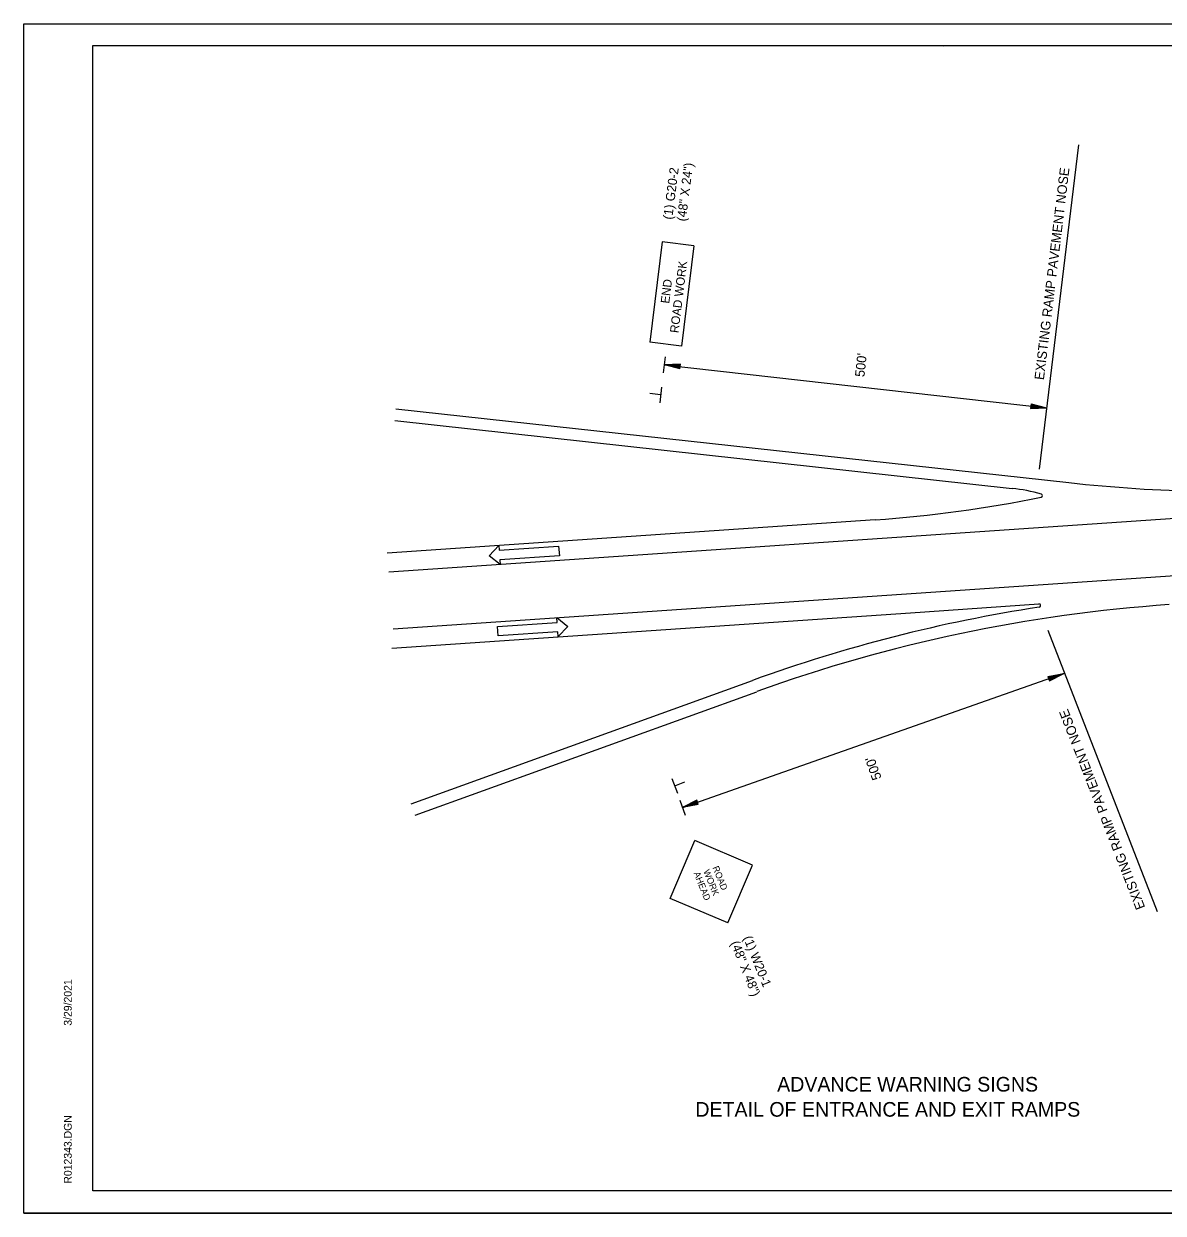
# Model space of a CAD drawing. Extents: x 1397271 to 1411271, y 376395 to 377888.
# Drawn here: x 1399604 to 1401035, y 376395 to 377888 of the extents above; entities that cross this region are included whole.
import ezdxf

# ---------------------------------------------------------------- set-up
doc = ezdxf.new("R2010")
doc.units = 0
for name, color, linetype in [('Default', 7, 'Continuous'), ('R_Border', 7, 'Continuous'), ('R_Draft', 7, 'Continuous'), ('R_Exist Surface', 7, 'Continuous'), ('R_MOT', 7, 'Continuous'), ('R_No Plot', 7, 'Continuous')]:
    doc.layers.add(name, color=color, linetype=linetype)

msp = doc.modelspace()

# ---------------------------------------------------------------- linework, layer by layer
at = {"layer": 'R_Border'}
for p, q in [((1399691.2, 377860.7), (1401904.5, 377860.7)), ((1399691.2, 376422.5), (1399691.2, 377860.7)), ((1400758.8, 377858.9), (1400758.8, 377858.9)), ((1400758.8, 377858.9), (1400758.8, 377858.9)), ((1399691.2, 376422.5), (1399691.2, 376422.5)), ((1401904.5, 376422.5), (1399691.2, 376422.5))]:
    msp.add_line(p, q, dxfattribs=at)
at = {"layer": 'R_Draft'}
for p, q in [((1400428.9, 377460.6), (1400408.7, 377459.8)), ((1400428.9, 377460.6), (1400408.7, 377459.8)), ((1400428.2, 377454.6), (1400408.7, 377459.8)), ((1400428.2, 377454.6), (1400408.7, 377459.8)), ((1400428.8, 377460.1), (1400412, 377459.4)), ((1400428.8, 377460.1), (1400412, 377459.4)), ((1400428.3, 377455.1), (1400412, 377459.4)), ((1400428.3, 377455.1), (1400412, 377459.4)), ((1400428.8, 377459.6), (1400415.4, 377459.1)), ((1400428.8, 377459.6), (1400415.4, 377459.1)), ((1400428.3, 377455.6), (1400415.4, 377459.1)), ((1400428.3, 377455.6), (1400415.4, 377459.1)), ((1400428.7, 377459.1), (1400418.7, 377458.7)), ((1400428.7, 377459.1), (1400418.7, 377458.7)), ((1400428.4, 377456.1), (1400418.7, 377458.7)), ((1400428.4, 377456.1), (1400418.7, 377458.7)), ((1400428.6, 377458.6), (1400422.1, 377458.3)), ((1400428.6, 377458.6), (1400422.1, 377458.3)), ((1400428.4, 377456.6), (1400422.1, 377458.3)), ((1400428.4, 377456.6), (1400422.1, 377458.3)), ((1400428.6, 377458), (1400425.4, 377457.9)), ((1400428.6, 377458), (1400425.4, 377457.9)), ((1400428.5, 377457.1), (1400425.4, 377457.9)), ((1400428.5, 377457.1), (1400425.4, 377457.9)), ((1400428.2, 377454.6), (1400428.9, 377460.6)), ((1400428.2, 377454.6), (1400428.9, 377460.6)), ((1400869.2, 377411), (1400868.6, 377405)), ((1400869.1, 377410), (1400882, 377406.5)), ((1400869.2, 377411), (1400888.8, 377405.8)), ((1400869.2, 377410.5), (1400885.4, 377406.1)), ((1400868.6, 377405.5), (1400885.4, 377406.1)), ((1400868.6, 377405), (1400888.8, 377405.8)), ((1400868.7, 377406.5), (1400878.7, 377406.9)), ((1400868.7, 377406), (1400882, 377406.5)), ((1400868.8, 377407.5), (1400872, 377407.6)), ((1400868.8, 377407), (1400875.3, 377407.3)), ((1400868.9, 377408.5), (1400872, 377407.6)), ((1400869, 377409), (1400875.3, 377407.3)), ((1400869.1, 377409.5), (1400878.7, 377406.9)), ((1400890.3, 377068.6), (1400910.2, 377072.4)), ((1400890.3, 377068.6), (1400892.3, 377063)), ((1400890.5, 377068.2), (1400907, 377071.3)), ((1400890.6, 377067.7), (1400903.8, 377070.2)), ((1400890.8, 377067.2), (1400900.6, 377069.1)), ((1400891, 377066.7), (1400897.4, 377068)), ((1400891.2, 377066.2), (1400894.3, 377066.8)), ((1400891.5, 377065.4), (1400894.3, 377066.8)), ((1400891.6, 377064.9), (1400897.4, 377068)), ((1400891.8, 377064.4), (1400900.6, 377069.1)), ((1400892, 377063.9), (1400903.8, 377070.2)), ((1400892.1, 377063.4), (1400907, 377071.3)), ((1400892.3, 377063), (1400910.2, 377072.4)), ((1400449.4, 376913.2), (1400431.5, 376903.8)), ((1400451.4, 376907.6), (1400431.5, 376903.8)), ((1400433.3, 376904.7), (1400431.5, 376903.8)), ((1400433.5, 376904.1), (1400431.5, 376903.8)), ((1400433.3, 376904.7), (1400431.8, 376903.9)), ((1400433.5, 376904.2), (1400431.8, 376903.9)), ((1400433.3, 376904.6), (1400432.2, 376904)), ((1400433.5, 376904.2), (1400432.2, 376904)), ((1400433.4, 376904.6), (1400432.5, 376904.1)), ((1400433.5, 376904.3), (1400432.5, 376904.1)), ((1400433.4, 376904.5), (1400432.8, 376904.2)), ((1400433.4, 376904.3), (1400432.8, 376904.2)), ((1400433.4, 376904.5), (1400433.1, 376904.3)), ((1400433.4, 376904.4), (1400433.1, 376904.3)), ((1400433.5, 376904.1), (1400433.3, 376904.7)), ((1400449.6, 376912.8), (1400434.7, 376904.9)), ((1400451.2, 376908), (1400434.7, 376904.9)), ((1400449.7, 376912.3), (1400437.9, 376906)), ((1400451, 376908.5), (1400437.9, 376906)), ((1400449.9, 376911.8), (1400441.1, 376907.1)), ((1400450.9, 376909), (1400441.1, 376907.1)), ((1400450.1, 376911.3), (1400444.3, 376908.2)), ((1400450.7, 376909.5), (1400444.3, 376908.2)), ((1400450.2, 376910.9), (1400447.4, 376909.4)), ((1400450.5, 376910), (1400447.4, 376909.4)), ((1400451.4, 376907.6), (1400449.4, 376913.2))]:
    msp.add_line(p, q, dxfattribs=at)
at = {"layer": 'R_Exist Surface'}
for p, q in [((1400071.7, 377404.7), (1400916.6, 377311.9)), ((1400070.4, 377389.7), (1400845.5, 377304.6)), ((1400062.7, 377199.7), (1401376.1, 377289.5)), ((1400060.8, 377223.6), (1400673.3, 377265.4)), ((1400068.1, 377128.3), (1401404.1, 377219.4)), ((1400717.9, 377148.6), (1400879.1, 377159.6)), ((1400066.4, 377104.2), (1400717.9, 377148.6)), ((1400090.9, 376908.4), (1400519.5, 377063.5)), ((1400096, 376894.3), (1400524.7, 377049.4))]:
    msp.add_line(p, q, dxfattribs=at)
for centre, radius, start, end in [((1401124.3, 379202.9), 1902.4, 263.7335, 273.9), ((1400567.5, 378831.4), 1569.7, 273.8643, 281.5623), ((1400822.9, 377088.4), 217.4, 74.1458, 84.0343), ((1400881.7, 377295.6), 2, 281.6258, 73.5312), ((1401172.3, 375260.7), 1902.4, 93.9033, 109.9033), ((1400879.3, 377157.6), 2, 278.7808, 93.9002), ((1401172.3, 375260.7), 1917.4, 98.7808, 109.9033)]:
    msp.add_arc(centre, radius, start, end, dxfattribs=at)
at = {"layer": 'R_MOT'}
for p, q in [((1400928.8, 377736.1), (1400879.4, 377328.8)), ((1400406, 377614.1), (1400390.5, 377488.3)), ((1400445.6, 377609.3), (1400406, 377614.1)), ((1400445.6, 377609.3), (1400430.1, 377483.4)), ((1400430.1, 377483.4), (1400390.5, 377488.3)), ((1400409.9, 377469.7), (1400407.4, 377449.9)), ((1400408.7, 377459.8), (1400888.8, 377405.8)), ((1400405.1, 377431.9), (1400402.9, 377412.2)), ((1400404, 377422.1), (1400390.3, 377423.6)), ((1400188.6, 377220.1), (1400200.9, 377233)), ((1400200.9, 377233), (1400201.3, 377227)), ((1400201.3, 377227), (1400276, 377232.1)), ((1400276, 377232.1), (1400276.9, 377220.1)), ((1400202.5, 377209), (1400188.6, 377220.1)), ((1400276.9, 377220.1), (1400202.1, 377215)), ((1400202.1, 377215), (1400202.5, 377209)), ((1400274, 377136.4), (1400273.6, 377142.4)), ((1400273.6, 377142.4), (1400287.5, 377131.3)), ((1400199.2, 377131.3), (1400274, 377136.4)), ((1400200.1, 377119.4), (1400199.2, 377131.3)), ((1400287.5, 377131.3), (1400275.2, 377118.5)), ((1400890.1, 377126.5), (1401027.6, 376773.6)), ((1400274.8, 377124.5), (1400200.1, 377119.4)), ((1400275.2, 377118.5), (1400274.8, 377124.5)), ((1400431.5, 376903.8), (1400911, 377072.8)), ((1400418.2, 376940.5), (1400425.3, 376921.9)), ((1400421.7, 376931.3), (1400434.6, 376936.2)), ((1400428.1, 376913.1), (1400435, 376894.4)), ((1400416, 376789.9), (1400446.8, 376862.4)), ((1400519.3, 376831.5), (1400446.8, 376862.4)), ((1400488.5, 376759), (1400519.3, 376831.5)), ((1400488.5, 376759), (1400416, 376789.9))]:
    msp.add_line(p, q, dxfattribs=at)
at = {"layer": 'R_No Plot'}
for p, q in [((1399604.3, 377888), (1401937.7, 377888)), ((1399604.3, 376394.6), (1401937.7, 376394.6))]:
    msp.add_line(p, q, dxfattribs=at)
for points in [[(1399604.3, 377888), (1401937.7, 377888), (1401937.7, 376394.6), (1399604.3, 376394.6)], [(1401328.6, 377860.7), (1401328.6, 377791.6), (1401578.8, 377791.6), (1401578.8, 377771.1), (1401741.2, 377771.1), (1401741.2, 377600.8), (1401904.5, 377600.8), (1401904.5, 376422.5), (1399691.2, 376422.5), (1399691.2, 377860.7)]]:
    msp.add_lwpolyline(points, close=True, dxfattribs=at)

# ---------------------------------------------------------------- texts
at = {"layer": 'Default'}
for s, p in [('ADVANCE WARNING SIGNS  ', (1400550.4, 376547.3)), ('DETAIL OF ENTRANCE AND EXIT RAMPS', (1400447.7, 376515.8))]:
    msp.add_text(s, height=18.375, dxfattribs=at).set_placement(p)
at = {"layer": 'R_Border'}
for s, p in [('3/29/2021', (1399664.5, 376630)), ('R012343.DGN', (1399664.5, 376431.7))]:
    msp.add_text(s, height=9.8, rotation=90, dxfattribs=at).set_placement(p)
at = {"layer": 'R_MOT'}
for s, height, rotation, p in [('(48" X 24")', 11.457, 82.6881, (1400435.6, 377639.5)), ('(1) G20-2', 11.46, 82.6881, (1400418.5, 377641.7)), ('EXISTING RAMP PAVEMENT NOSE', 12, 83.096, (1400885.3, 377440.3)), ('ROAD WORK', 10.83, 82.996, (1400426.4, 377499.3)), ('END', 10.83, 82.996, (1400414.8, 377536.3)), ("500'", 12, 83.8888, (1400659.9, 377444)), ('EXISTING RAMP PAVEMENT NOSE', 12, 111.285, (1401012.7, 376778.6)), ("500'", 12, 109.4135, (1400681.7, 376940.9)), ('ROAD', 8.21, 291.9291, (1400469, 376828.6)), ('AHEAD', 8.21, 291.9292, (1400445.4, 376821.4)), ('WORK', 8.21, 291.9287, (1400457.5, 376824.1)), ('(1) W20-1', 11.4, 291.9287, (1400507.6, 376740.3)), ('(48" X 48")', 11.4, 291.9287, (1400491.7, 376733.9))]:
    msp.add_text(s, height=height, rotation=rotation, dxfattribs=at).set_placement(p)

doc.saveas('drawing.dxf')
